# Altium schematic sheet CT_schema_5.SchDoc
size 368 x 245 mm
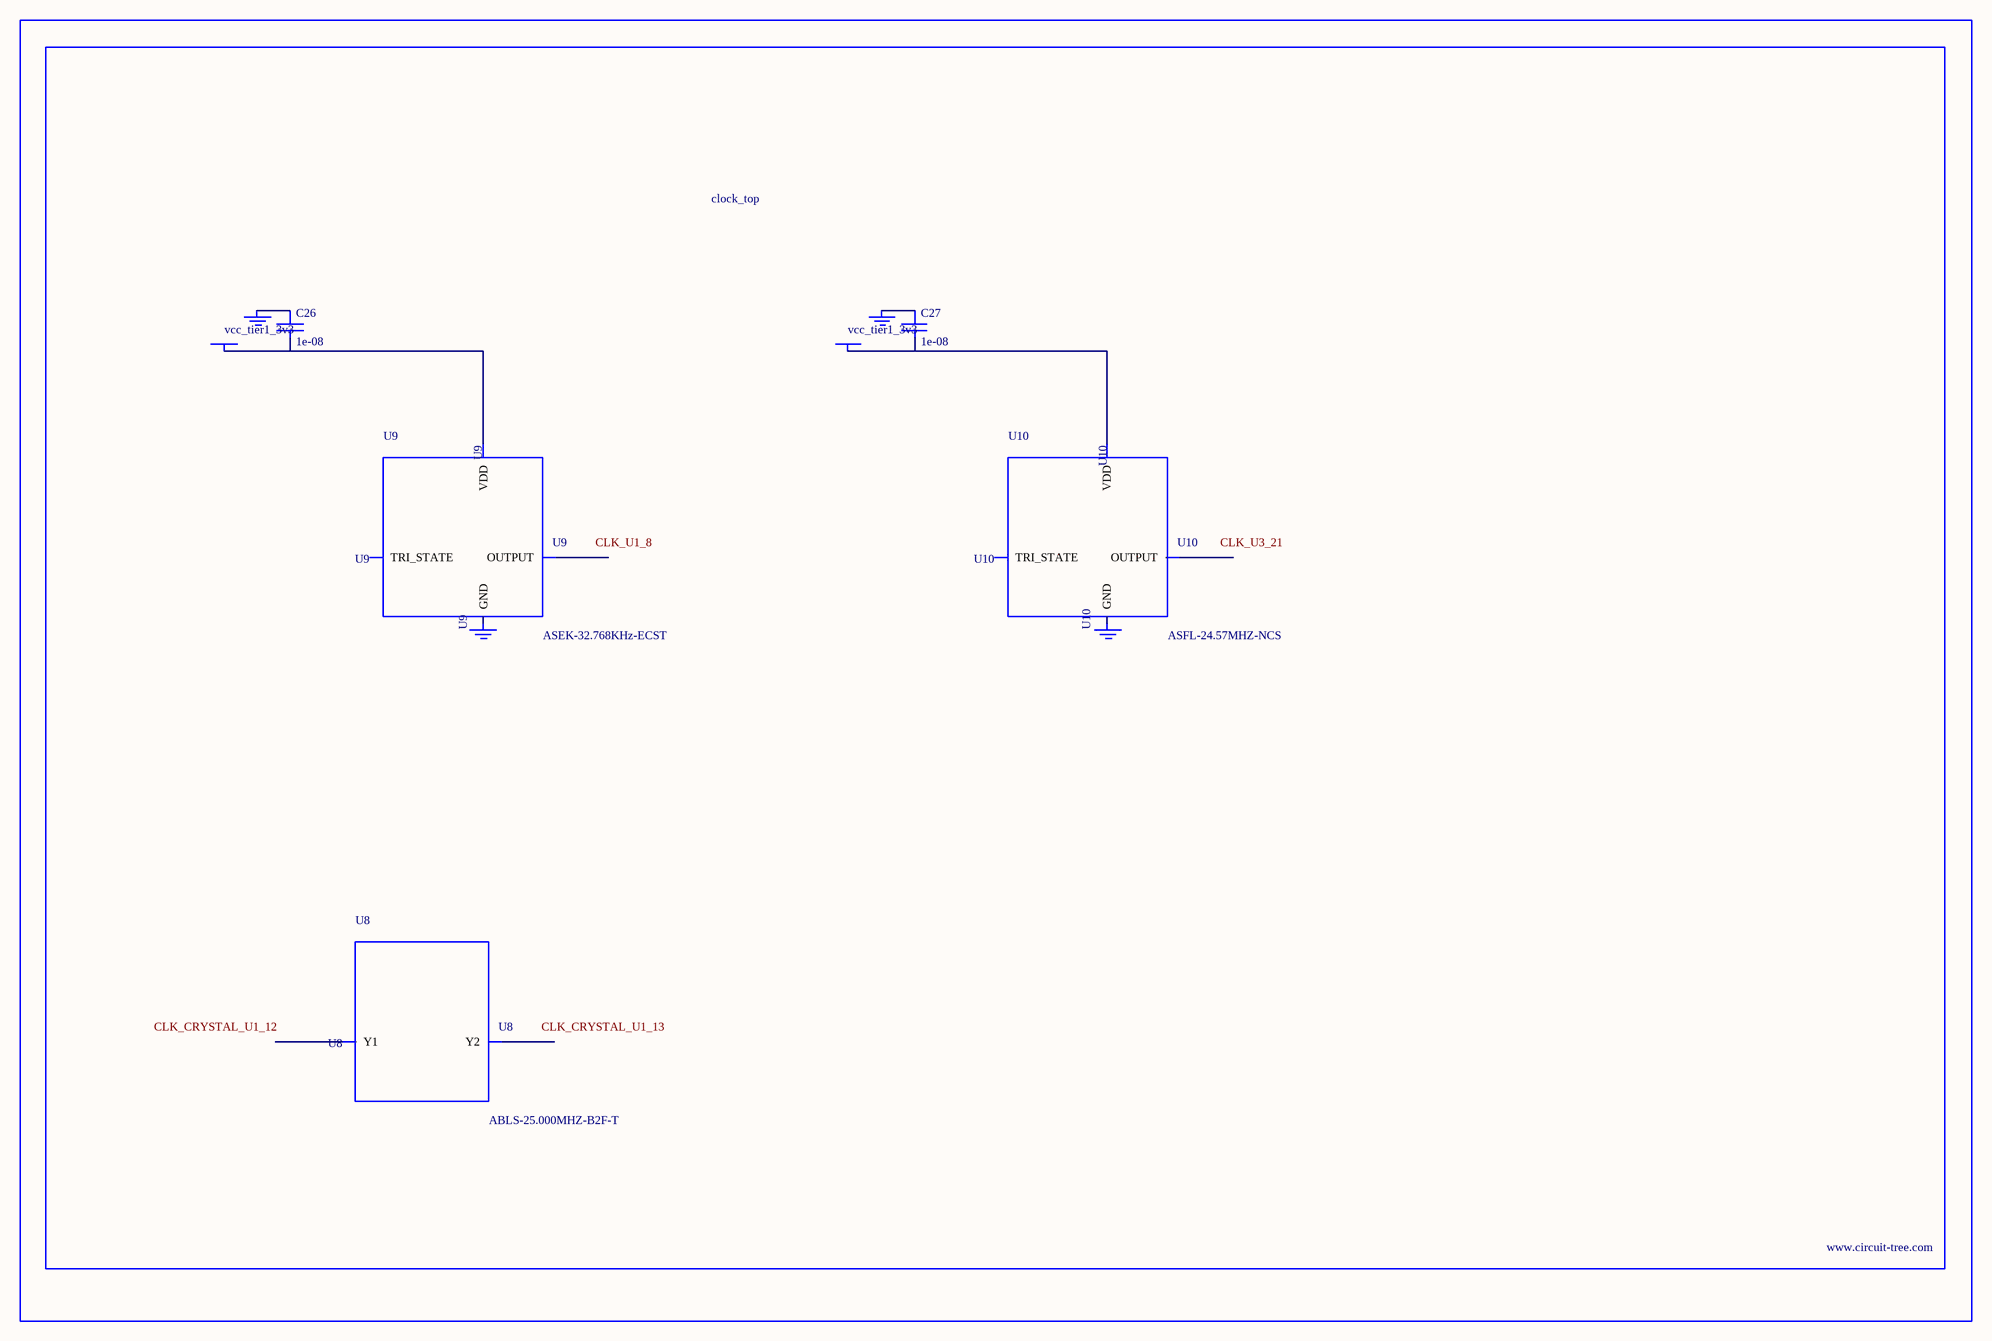
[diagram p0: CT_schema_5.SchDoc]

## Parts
BORDER4  (no value)
C26  1e-08  [C0402]
C27  1e-08  [C0402]
GND_INSTANCE_4_0  (no value)
GND_INSTANCE_4_1  (no value)
GND_INSTANCE_4_2  (no value)
GND_INSTANCE_4_3  (no value)
POWER_INSTANCE_4_0  vcc_tier1_3v3
POWER_INSTANCE_4_1  vcc_tier1_3v3
U8  ABLS-25.000MHZ-B2F-T  [ABLS-25.000MHZ-B2F-T]
U9  ASEK-32.768KHz-ECST  [ASEK]
U10  ASFL-24.57MHZ-NCS  [ASFL1]

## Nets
NetC26_1: C26.1 GND_INSTANCE_4_0.0(GND)
NetC26_2: C26.2 POWER_INSTANCE_4_0.0(PWR) U9.4(VDD)
NetC27_1: C27.1 GND_INSTANCE_4_2.0(GND)
NetC27_2: C27.2 POWER_INSTANCE_4_1.0(PWR) U10.4(VDD)

Not connected (* = marked no-connect by the designer): GND_INSTANCE_4_1 0(GND); GND_INSTANCE_4_3 0(GND); U8 1(Y1) 2(Y2); U9 1(TRI_STATE) 2(GND) 3(OUTPUT); U10 1(TRI_STATE) 2(GND) 3(OUTPUT)

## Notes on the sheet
- Labels drawn without touching a wire or pin: CLK_CRYSTAL_U1_12, CLK_CRYSTAL_U1_13, CLK_U1_8, CLK_U3_21

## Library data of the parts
BORDER4 = BORDER_PAGE4
C26 C27 = C0402C103K3RAC
GND_INSTANCE_4_0-GND_INSTANCE_4_3 = GND
POWER_INSTANCE_4_0 POWER_INSTANCE_4_1 = PWR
